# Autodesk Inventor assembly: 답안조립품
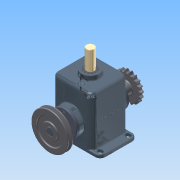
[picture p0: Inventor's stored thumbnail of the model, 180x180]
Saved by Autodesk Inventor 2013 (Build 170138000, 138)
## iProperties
Created: 2015-03
Part Number: 답안조립품
Document SubType Name: Assembly
Designer: Administrator
Mass: 8579 g
Surface Area: 4386.44 cm^2
Volume: 1982.5 cm^3
Density: 4.32736 g/cm^3
Author: Administrator
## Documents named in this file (15)
- C:\Documents and Settings\Administrator\바탕 화면\350305V1012\답안조립품.iam
- C:\Documents and Settings\Administrator\바탕 화면\350305V1012\본체.ipt
- C:\Documents and Settings\Administrator\바탕 화면\350305V1012\베어링 6205.ipt
- C:\Documents and Settings\Administrator\바탕 화면\350305V1012\편심축.ipt
- C:\Documents and Settings\Administrator\바탕 화면\350305V1012\키 8x8.ipt
- C:\Documents and Settings\Administrator\바탕 화면\350305V1012\커버.ipt
- C:\Documents and Settings\Administrator\바탕 화면\350305V1012\M4x0.5.ipt
- C:\Documents and Settings\Administrator\바탕 화면\350305V1012\멈춤링.ipt
- C:\Documents and Settings\Administrator\바탕 화면\350305V1012\오일실.ipt
- C:\Documents and Settings\Administrator\바탕 화면\350305V1012\V-벨트풀리.ipt
- C:\Documents and Settings\Administrator\바탕 화면\350305V1012\체인 스프로킷.ipt
- C:\Documents and Settings\Administrator\바탕 화면\350305V1012\멈춤나사 M5x0.5.ipt
- C:\Documents and Settings\Administrator\바탕 화면\350305V1012\가변스프링.ipt
- C:\Documents and Settings\Administrator\바탕 화면\350305V1012\부시.ipt
- C:\Documents and Settings\Administrator\바탕 화면\350305V1012\슬라이드.ipt
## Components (9 placed, 4 different names)
1. V-벨트풀리:1 — 플러쉬:3, 각도:3
2. 5-체인 스프로킷:1 — 플러쉬:4, 각도:4
3. 가변스프링:1
4. M4x0.5:1
5. M4x0.5:3
6. M4x0.5:4
7. M4x0.5:2
8. M4x0.5:5
9. M4x0.5:6
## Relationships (4: Flush 2, Angle 2)
- 플러쉬:3 [Flush]: V-벨트풀리:1
- 각도:3 [Angle]: V-벨트풀리:1
- 플러쉬:4 [Flush]: 5-체인 스프로킷:1
- 각도:4 [Angle]: 5-체인 스프로킷:1
